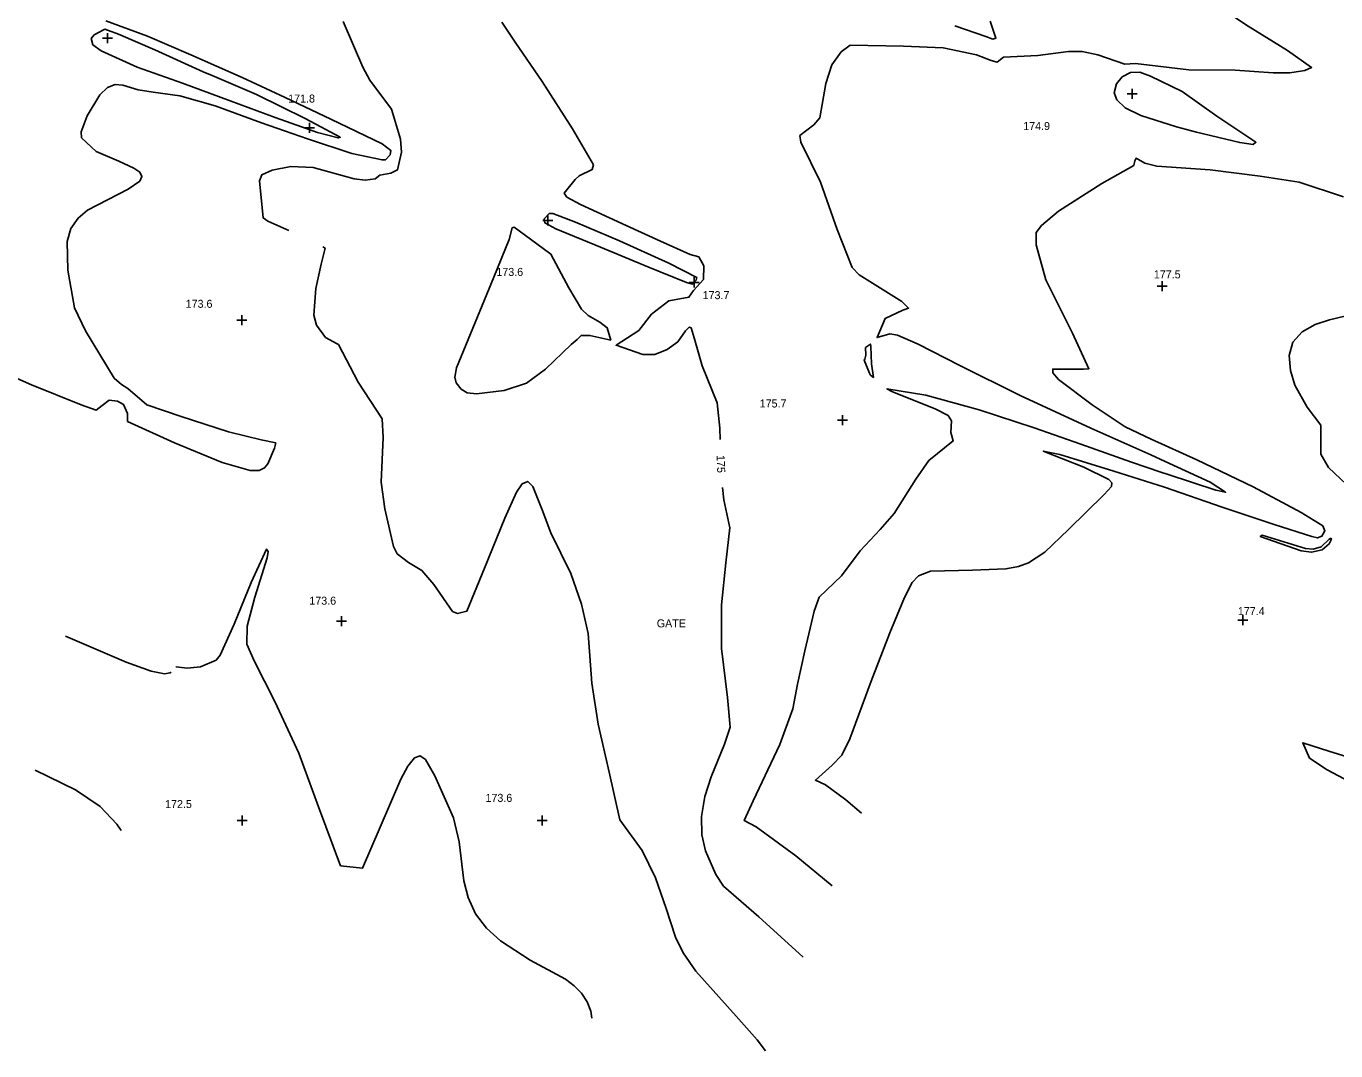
# Model space of a CAD drawing. Extents: x 1467615 to 2003689, y 770235 to 1108726.
# Drawn here: x 1996471.1 to 1996798.3, y 776167.5 to 776423.4 of the extents above; entities that cross this region are included whole.
import ezdxf

# ---------------------------------------------------------------- set-up
doc = ezdxf.new("R2010")
doc.units = 0
for name, color, linetype in [('RD_DTM_Major1', 7, 'Continuous'), ('RD_DTM_Major1_Lbl', 7, 'Continuous'), ('RD_DTM_Minor1', 7, 'Continuous'), ('RD_DTM_Spot_Elev', 7, 'Continuous'), ('RD_TX_Misc1', 7, 'Continuous')]:
    doc.layers.add(name, color=color, linetype=linetype)

msp = doc.modelspace()

# ---------------------------------------------------------------- linework, layer by layer
at = {"layer": 'RD_DTM_Major1'}
for points in [[(1996589.87, 776424.37), (1996593.27, 776419.41), (1996600.02, 776409.55), (1996607.56, 776397.77), (1996612.78, 776388.77), (1996612.5, 776387.58), (1996609.24, 776386.04), (1996608.22, 776385.11), (1996606.14, 776382.53), (1996605.52, 776381.64), (1996606.12, 776380.7), (1996609.56, 776378.88), (1996620.98, 776373.62), (1996629.53, 776369.67), (1996636.99, 776366.36), (1996639.1, 776365.78), (1996640.34, 776363.57), (1996640.3, 776360.15), (1996637.78, 776357.33), (1996636.66, 776355.7), (1996631.66, 776354.76), (1996627.34, 776351.48), (1996624.17, 776347.4), (1996618.47, 776343.71), (1996625.13, 776341.38), (1996628.14, 776341.38), (1996631.25, 776342.6), (1996633.92, 776344.57), (1996635.81, 776347.26), (1996636.75, 776348.25), (1996637.19, 776348.02), (1996637.98, 776345.56), (1996639.98, 776338.58), (1996643.67, 776329.3), (1996644.35, 776322.99), (1996644.44, 776320.19)], [(1996711.9, 776424.59), (1996713.37, 776420.36), (1996712.59, 776420.12), (1996710.81, 776420.76), (1996703.1, 776423.46)], [(1996596.08, 776334.22), (1996600.78, 776337.76), (1996607.22, 776343.92), (1996608.77, 776345.15), (1996609.75, 776346.11), (1996611.91, 776346.14), (1996617.11, 776344.98), (1996616.22, 776348.06), (1996614.4, 776349.48), (1996611.48, 776351.11), (1996609.84, 776352.73), (1996606.62, 776358.06), (1996602.18, 776366.48), (1996597.1, 776370.15), (1996593.02, 776373.2), (1996592.51, 776373.03), (1996591.75, 776370.14), (1996587.93, 776360.68), (1996583.82, 776350.8), (1996578.56, 776338.03), (1996578.15, 776335.72), (1996578.46, 776334.3), (1996579.77, 776332.74), (1996581.27, 776331.84), (1996583.55, 776331.57), (1996590.53, 776332.37), (1996596.08, 776334.22)], [(1996645.05, 776308.2), (1996645.35, 776305.08), (1996646.87, 776298.1), (1996645.88, 776289.36), (1996644.81, 776278.89), (1996644.78, 776268), (1996646.3, 776255.77), (1996646.94, 776248.3), (1996645.57, 776244.12), (1996642.22, 776235.94), (1996640.65, 776231.01), (1996639.77, 776226.06), (1996639.9, 776221.47), (1996640.79, 776217.42), (1996643.35, 776211.5), (1996645.26, 776208.65), (1996654.16, 776200.93), (1996665.22, 776190.92)]]:
    msp.add_lwpolyline(points, dxfattribs=at)
at = {"layer": 'RD_DTM_Minor1'}
for points in [[(1996770.48, 776427.27), (1996776.39, 776423.36), (1996786.17, 776417.28), (1996792.23, 776413.07), (1996790.52, 776412.31), (1996786.8, 776411.72), (1996782.59, 776411.74), (1996773.13, 776412.42), (1996761.56, 776412.5), (1996748.23, 776414.05), (1996745.58, 776413.93), (1996738.86, 776416.19), (1996734.89, 776417.07), (1996731.51, 776417.02), (1996723.81, 776416.08), (1996715.22, 776415.6), (1996713.63, 776414.4), (1996712.2, 776414.81), (1996708.52, 776416.22), (1996700.15, 776418.01), (1996690.26, 776418.37), (1996676.94, 776418.62), (1996674.73, 776416.95), (1996672.35, 776413.7), (1996670.86, 776409.07), (1996669.38, 776400.53), (1996667.86, 776398.72), (1996664.36, 776396.05), (1996664.63, 776394.44), (1996669.5, 776384.42), (1996673.68, 776372.57), (1996677.4, 776363.11), (1996679.16, 776361.28), (1996689.87, 776354.65), (1996691.52, 776352.99), (1996690.07, 776352.42), (1996685.67, 776350.41), (1996683.68, 776345.6), (1996686.85, 776346.57), (1996688.8, 776346.22), (1996693.96, 776343.96), (1996704.35, 776338.64), (1996719.4, 776331.14), (1996737.05, 776323.01), (1996752.09, 776316.37), (1996755.65, 776314.71)], [(1996490.98, 776424.73), (1996501.38, 776420.87), (1996512.17, 776416.19), (1996525, 776410.57), (1996535.74, 776405.58), (1996547.22, 776400.15), (1996560.02, 776394.02), (1996562.15, 776392.37), (1996562.01, 776391.28), (1996560.88, 776390.02), (1996559.97, 776389.98), (1996552.42, 776391.6), (1996541.32, 776395.24), (1996529.89, 776399.28), (1996518.31, 776403.48), (1996509.49, 776406.01), (1996502.78, 776406.88), (1996499.03, 776407.45), (1996495.24, 776408.67), (1996493.32, 776408.79), (1996491.39, 776408.06), (1996489.5, 776406.23), (1996486.31, 776400.95), (1996484.77, 776396.98), (1996484.87, 776395.5), (1996488.53, 776392.08), (1996494.21, 776389.69), (1996498, 776387.93), (1996499.42, 776386.9), (1996499.99, 776385.82), (1996499.47, 776384.71), (1996496.56, 776382.69), (1996486.41, 776377.46), (1996484.01, 776375.46), (1996482.19, 776372.84), (1996481.29, 776369.59), (1996481.43, 776362.49), (1996483.13, 776353.06), (1996485.88, 776347.33), (1996493.02, 776335.48), (1996494.86, 776333.93), (1996496.46, 776332.91), (1996501.24, 776328.83), (1996509.75, 776325.94), (1996521.61, 776322.08), (1996529.8, 776320.08), (1996533.4, 776319.32), (1996533.07, 776317.97), (1996531.45, 776314.07), (1996530.63, 776313.07), (1996529.24, 776312.43), (1996527.04, 776312.4), (1996520.01, 776314.44), (1996508.12, 776319.32), (1996496.39, 776324.67), (1996496.4, 776326.64), (1996495.4, 776328.94), (1996493.86, 776329.71), (1996491.8, 776330.02), (1996490.06, 776328.69), (1996488.56, 776327.45), (1996484.82, 776328.86), (1996472.4, 776333.8), (1996464.39, 776337.34)], [(1996517.56, 776411.04), (1996528.6, 776406.28), (1996540.91, 776400.22), (1996549.54, 776395.63), (1996548.99, 776395.48), (1996543.86, 776396.85), (1996533.25, 776400.54), (1996522, 776404.75), (1996510.09, 776409.16), (1996498.83, 776413.15), (1996489.77, 776417.21), (1996487.71, 776418.75), (1996487.33, 776420.31), (1996488.05, 776421.24), (1996490.7, 776422.59), (1996494.13, 776421.37), (1996503.2, 776417.43), (1996515.3, 776412), (1996517.56, 776411.04)], [(1996550.3, 776424.55), (1996555.15, 776413.13), (1996556.92, 776409.86), (1996562.31, 776402.67), (1996564.62, 776395.18), (1996564.85, 776391.92), (1996563.8, 776387.5), (1996562.14, 776386.68), (1996559.46, 776386.19), (1996558.25, 776385.26), (1996555.77, 776384.93), (1996552.98, 776385.22), (1996542.73, 776388.05), (1996537.15, 776388.34), (1996532.51, 776387.43), (1996529.94, 776386.25), (1996529.38, 776384.78), (1996530.28, 776375.51), (1996531.44, 776374.66), (1996536.68, 776372.34)], [(1996758.5, 776398.26), (1996749.59, 776401.09), (1996745.65, 776402.96), (1996743.54, 776405), (1996742.9, 776406.74), (1996743.48, 776408.96), (1996744.87, 776410.7), (1996746.95, 776411.78), (1996749.28, 776411.87), (1996751.97, 776410.88), (1996759.9, 776407.09), (1996768.57, 776400.89), (1996778.32, 776394.4), (1996777.64, 776393.85), (1996774.3, 776394.29), (1996763.5, 776396.9), (1996758.5, 776398.26)], [(1996800.23, 776380.73), (1996789.13, 776384.45), (1996779.37, 776385.92), (1996766.86, 776387.52), (1996753.55, 776388.41), (1996750.53, 776389.17), (1996748.38, 776390.4), (1996748.08, 776389.72), (1996747.85, 776388.61), (1996739.8, 776384.07), (1996729, 776377.17), (1996724.75, 776373.61), (1996723.44, 776371.86), (1996723.44, 776368.81), (1996725.85, 776360.04), (1996732.46, 776346.74), (1996736.58, 776337.85), (1996735.23, 776337.69), (1996727.56, 776337.76), (1996727.55, 776336.82), (1996729.03, 776335.17), (1996737.38, 776328.78), (1996745.62, 776323.33), (1996752.12, 776320.23), (1996763.57, 776315.07), (1996777.6, 776308.38), (1996789.66, 776301.96), (1996795, 776298.59), (1996795.57, 776297.35), (1996794.82, 776296.02), (1996793.7, 776295.6), (1996792.28, 776295.92), (1996782.89, 776298.96), (1996769.87, 776303.3), (1996755.44, 776308.24), (1996742.8, 776312.26), (1996729.34, 776316.4), (1996725.18, 776317.25), (1996735.31, 776313.23), (1996741.57, 776310.2), (1996742.29, 776309.32), (1996742.23, 776308.46), (1996740.42, 776306.39), (1996731.51, 776297.71), (1996725.56, 776292.06), (1996721.53, 776289.33), (1996719.01, 776288.42), (1996715.84, 776287.83), (1996707.52, 776287.55), (1996696.98, 776287.25), (1996694.02, 776286.15), (1996692.44, 776284.46), (1996690.51, 776280.71), (1996686.88, 776271.92), (1996682.16, 776259.85), (1996676.84, 776245.42), (1996674.85, 776241.35), (1996672.47, 776238.82), (1996668.27, 776235.13), (1996670.79, 776233.95), (1996675.82, 776230.18), (1996679.77, 776226.88)], [(1996638.45, 776359.98), (1996637.53, 776358.98), (1996636.06, 776359.33), (1996626.42, 776363.29), (1996614.52, 776368.16), (1996603.4, 776372.76), (1996600.67, 776374.26), (1996600.48, 776375.26), (1996601.75, 776376.58), (1996602.64, 776376.6), (1996608.29, 776374.45), (1996619.3, 776369.8), (1996631.62, 776364.16), (1996638.62, 776360.6), (1996638.45, 776359.98)], [(1996545.19, 776368.25), (1996545.74, 776367.98), (1996544.79, 776363.97), (1996543.4, 776357.85), (1996542.92, 776351.18), (1996543.56, 776348.7), (1996545.88, 776345.65), (1996548.74, 776344.09), (1996549.13, 776343.88), (1996553.97, 776334.45), (1996559.99, 776325.31), (1996560.25, 776320.69), (1996559.78, 776309.55), (1996560.71, 776302.82), (1996562.8, 776293.47), (1996563.75, 776291.63), (1996566.57, 776289.47), (1996569.92, 776287.49), (1996572.94, 776283.97), (1996577.6, 776277.19), (1996578.83, 776276.72), (1996581.2, 776277.28), (1996585.56, 776288), (1996590.68, 776300.56), (1996593.57, 776307.03), (1996595, 776309.12), (1996596.37, 776309.71), (1996597.64, 776308.45), (1996599.95, 776302.6), (1996602.15, 776296.86), (1996607.17, 776286.71), (1996609.84, 776279.08), (1996611.48, 776271.74), (1996612.41, 776259.32), (1996613.96, 776249.04), (1996616.74, 776237.07), (1996619.42, 776225.21), (1996625.01, 776217.56), (1996628.29, 776210.73), (1996630.99, 776203.04), (1996633.28, 776195.85), (1996635.23, 776191.94), (1996638.39, 776187.41), (1996648.42, 776176.2), (1996653.68, 776170.27), (1996655.75, 776167.51)], [(1996802.58, 776351.46), (1996796.7, 776350.08), (1996793.11, 776348.84), (1996789.86, 776347.03), (1996787.55, 776344.49), (1996786.65, 776341.17), (1996786.93, 776337.43), (1996788.02, 776333.73), (1996791.13, 776328.21), (1996794.5, 776323.77), (1996794.53, 776320.29), (1996794.58, 776316.47), (1996796.43, 776313.18), (1996802.35, 776307.57)], [(1996682.04, 776336.24), (1996682.77, 776335.67), (1996682.24, 776339.06), (1996682.12, 776343.38), (1996681.99, 776344), (1996680.77, 776343.1), (1996680.87, 776341.23), (1996680.62, 776340.24), (1996680.44, 776339.96), (1996681.81, 776336.74), (1996682.04, 776336.24)], [(1996754.59, 776312.02), (1996747.26, 776314.49), (1996734.6, 776319), (1996722.95, 776323.11), (1996709.16, 776327.59), (1996695.82, 776331.23), (1996686.14, 776332.82), (1996687.36, 776332.13), (1996698.37, 776327.72), (1996701.39, 776326.12), (1996702.26, 776324.81), (1996702.12, 776321.88), (1996702.71, 776319.82), (1996696.56, 776314.88), (1996693.38, 776310.29), (1996687.94, 776301.66), (1996684.4, 776297.72), (1996679.46, 776292.32), (1996674.75, 776286.14), (1996669.17, 776280.81), (1996667.91, 776277.33), (1996665.59, 776267.36), (1996663.81, 776259.03), (1996662.63, 776252.87), (1996659.39, 776244), (1996652.67, 776229.92), (1996650.45, 776225.04), (1996653.49, 776223.43), (1996663.34, 776216.16), (1996672.43, 776208.74)], [(1996755.65, 776314.71), (1996766.87, 776309.49), (1996770.76, 776307), (1996768.27, 776307.49), (1996756.41, 776311.4), (1996754.59, 776312.02)], [(1996797.04, 776295.53), (1996796.63, 776295.24), (1996794.65, 776293.33), (1996792.61, 776292.8), (1996790.67, 776292.91), (1996779.91, 776296.24), (1996779.41, 776295.98), (1996789.63, 776292.35), (1996792.21, 776292.01), (1996794.84, 776292.58), (1996796.66, 776294.08), (1996797.18, 776295.28), (1996797.04, 776295.53)], [(1996508.46, 776263.28), (1996508.55, 776263.37), (1996511.27, 776263.03), (1996514.62, 776263.41), (1996518.49, 776265.07), (1996519.55, 776266.3), (1996523.04, 776274.07), (1996527.28, 776284.44), (1996531.1, 776292.8), (1996531.53, 776292.17), (1996531.28, 776290.62), (1996528.2, 776280.75), (1996526.31, 776273.56), (1996526.22, 776269.07), (1996528.02, 776264.91), (1996533.15, 776254.73), (1996539.18, 776241.84), (1996544.11, 776228.42), (1996549.6, 776213.74), (1996555.13, 776213.09), (1996559.5, 776223.37), (1996564.69, 776235.36), (1996566.45, 776238.63), (1996568.09, 776240.68), (1996569.53, 776241.15), (1996570.82, 776240.29), (1996573.2, 776236.16), (1996577.87, 776225.69), (1996579.25, 776219.69), (1996580.44, 776209.97), (1996581.51, 776205.78), (1996583.34, 776201.72), (1996586.1, 776198.1), (1996589.54, 776194.98), (1996596.98, 776190.13), (1996605.82, 776185.36), (1996607.99, 776183.76), (1996609.78, 776181.88), (1996611.19, 776179.73), (1996612.18, 776177.37), (1996612.42, 776175.67)], [(1996480.89, 776271.05), (1996496.01, 776264.53), (1996502.29, 776262.34), (1996505.66, 776261.65), (1996507.07, 776261.89), (1996507.26, 776262.09)], [(1996804.36, 776239.91), (1996796.55, 776242.32), (1996790.01, 776244.42), (1996791.73, 776240.6), (1996796.14, 776237.71), (1996805.89, 776232.53)], [(1996473.33, 776237.63), (1996483.42, 776232.66), (1996489.58, 776228.49), (1996493.68, 776224.1), (1996494.77, 776222.5)]]:
    msp.add_lwpolyline(points, dxfattribs=at)
at = {"layer": 'RD_DTM_Spot_Elev'}
for p, q in [((1996490.12, 776420.41), (1996492.62, 776420.41)), ((1996491.37, 776419.16), (1996491.37, 776421.66)), ((1996746.11, 776406.51), (1996748.61, 776406.51)), ((1996747.36, 776405.26), (1996747.36, 776407.76)), ((1996541.85, 776396.76), (1996541.85, 776399.26)), ((1996540.6, 776398.01), (1996543.1, 776398.01)), ((1996600.18, 776374.87), (1996602.68, 776374.87)), ((1996601.43, 776373.62), (1996601.43, 776376.12)), ((1996637.99, 776358.16), (1996637.99, 776360.66)), ((1996636.74, 776359.41), (1996639.24, 776359.41)), ((1996753.61, 776358.47), (1996756.11, 776358.47)), ((1996754.86, 776357.22), (1996754.86, 776359.72)), ((1996524.96, 776348.69), (1996524.96, 776351.19)), ((1996523.71, 776349.94), (1996526.21, 776349.94)), ((1996673.75, 776325), (1996676.25, 776325)), ((1996675, 776323.75), (1996675, 776326.25)), ((1996549.84, 776273.53), (1996549.84, 776276.03)), ((1996773.79, 776275.05), (1996776.29, 776275.05)), ((1996775.04, 776273.8), (1996775.04, 776276.3)), ((1996548.59, 776274.78), (1996551.09, 776274.78)), ((1996525, 776223.75), (1996525, 776226.25)), ((1996600, 776223.75), (1996600, 776226.25)), ((1996523.75, 776225), (1996526.25, 776225)), ((1996598.75, 776225), (1996601.25, 776225))]:
    msp.add_line(p, q, dxfattribs=at)

# ---------------------------------------------------------------- texts
at = {"layer": 'RD_DTM_Major1_Lbl'}
msp.add_text('175', height=2, rotation=271.9502, dxfattribs=at).set_placement((1996643.58, 776316.24))
at = {"layer": 'RD_DTM_Spot_Elev'}
for s, p in [('171.8', (1996536.52, 776404.31)), ('174.9', (1996720.18, 776397.44)), ('173.6', (1996588.54, 776361.01)), ('177.5', (1996752.82, 776360.4)), ('173.7', (1996640.08, 776355.21)), ('173.6', (1996510.91, 776353.05)), ('175.7', (1996654.33, 776328.16)), ('173.6', (1996541.81, 776278.91)), ('177.4', (1996773.8, 776276.3)), ('172.5', (1996505.77, 776228.13)), ('173.6', (1996585.82, 776229.67))]:
    msp.add_text(s, height=2, dxfattribs=at).set_placement(p)
at = {"layer": 'RD_TX_Misc1'}
msp.add_text('GATE', height=2, dxfattribs=at).set_placement((1996628.62, 776273.25))

doc.saveas('drawing.dxf')
